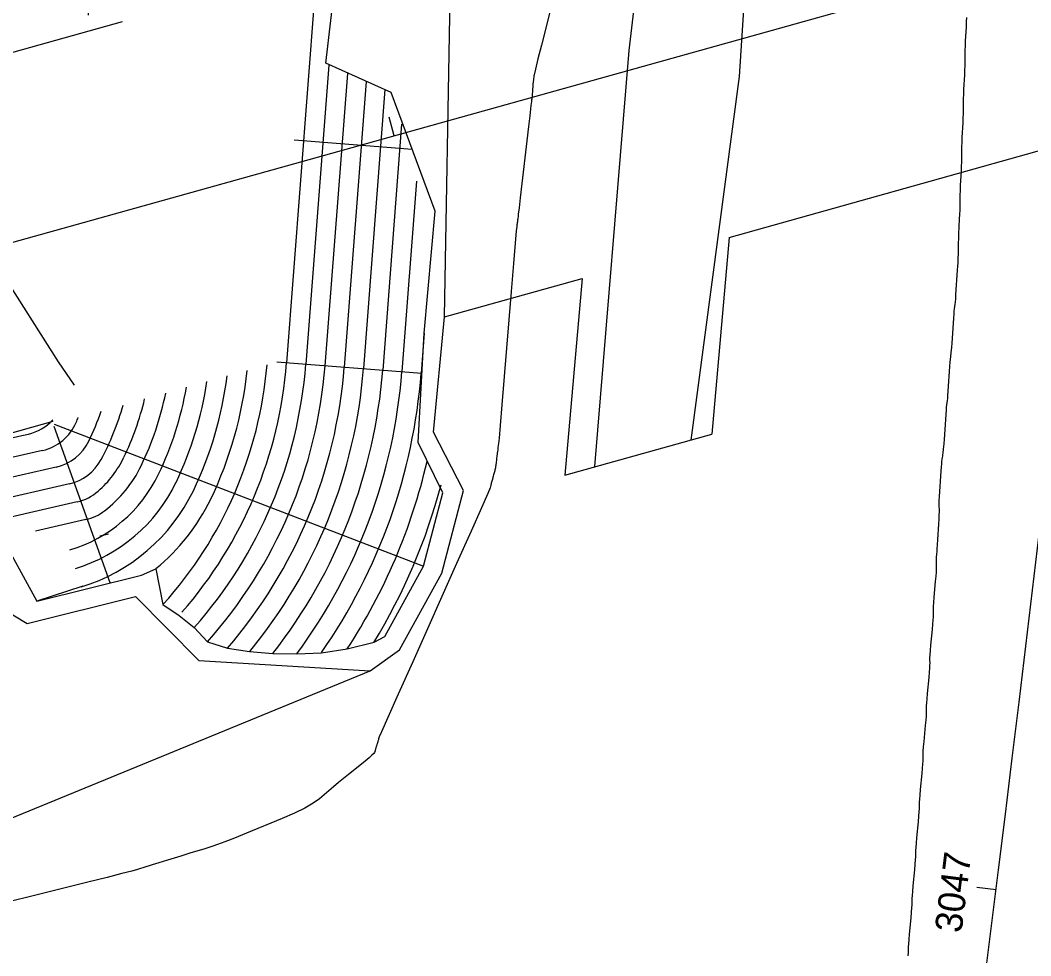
# Model space of a CAD drawing. Extents: x 1512289 to 1544686, y 552531 to 589211.
# Drawn here: x 1543120 to 1543224.9, y 587283 to 587380.1 of the extents above; entities that cross this region are included whole.
import ezdxf

# ---------------------------------------------------------------- set-up
doc = ezdxf.new("R2010")
doc.units = 0
for name, color, linetype in [('DR_X_Flood_Boundary', 7, 'Continuous'), ('DT_P_Break_Line', 7, 'Continuous'), ('DT_P_Contour_Major', 7, 'Continuous'), ('DT_P_Contour_Minor', 7, 'Continuous'), ('DT_P_Graded_Shoulder', 7, 'Continuous'), ('DT_P_Slope_Break_Line', 7, 'Continuous'), ('GE_X_CL_20', 7, 'Continuous'), ('GK_Visualization', 7, 'Continuous'), ('RD_P_Fence', 7, 'Continuous'), ('RW_P_Const_Limits', 7, 'Continuous'), ('SC_Scratch1', 7, 'Continuous'), ('SC_Scratch2', 7, 'Continuous')]:
    doc.layers.add(name, color=color, linetype=linetype)

msp = doc.modelspace()

# ---------------------------------------------------------------- linework, layer by layer
at = {"layer": 'DR_X_Flood_Boundary'}
for points in [[(1543175.17, 587381.74), (1543174.09, 587377.47), (1543173.73, 587376.04), (1543173.47, 587374.97), (1543173.31, 587374.26), (1543173.25, 587373.91), (1543173.21, 587373.44), (1543173.2, 587373.27), (1543173.18, 587373.1), (1543173.17, 587372.93), (1543173.16, 587372.76), (1543173.12, 587372.3), (1543173.11, 587372.15), (1543173.11, 587372.05), (1543173.1, 587371.98), (1543173.1, 587371.96), (1543173.1, 587371.96), (1543173.1, 587371.94), (1543173.09, 587371.88), (1543173.07, 587371.78), (1543173.06, 587371.64), (1543173, 587371.22), (1543172.95, 587370.87), (1543172.87, 587370.14), (1543172.74, 587369.04), (1543172.57, 587367.56), (1543172.06, 587363.12), (1543171.89, 587361.65), (1543171.77, 587360.59), (1543171.69, 587359.93), (1543171.66, 587359.68), (1543171.64, 587359.54), (1543171.64, 587359.49), (1543171.63, 587359.44), (1543171.62, 587359.39), (1543171.62, 587359.34), (1543171.6, 587359.22), (1543171.59, 587359.17), (1543171.59, 587359.12), (1543171.58, 587359.08), (1543171.58, 587359.04), (1543171.56, 587358.92), (1543171.55, 587358.88), (1543171.55, 587358.83), (1543171.54, 587358.79), (1543171.54, 587358.75), (1543171.52, 587358.65), (1543171.48, 587358.2), (1543171.38, 587356.93), (1543171.2, 587354.84), (1543170.96, 587351.93), (1543170.22, 587343.09), (1543169.98, 587340.16), (1543169.8, 587338.03), (1543169.69, 587336.7), (1543169.63, 587336.15), (1543169.58, 587335.75), (1543169.56, 587335.6), (1543169.55, 587335.45), (1543169.53, 587335.31), (1543169.51, 587335.17), (1543169.46, 587334.79), (1543169.44, 587334.65), (1543169.43, 587334.51), (1543169.41, 587334.38), (1543169.39, 587334.24), (1543169.35, 587333.89), (1543169.33, 587333.77), (1543169.32, 587333.69), (1543169.31, 587333.63), (1543169.31, 587333.61), (1543169.3, 587333.59), (1543169.3, 587333.57), (1543169.29, 587333.52), (1543169.27, 587333.44), (1543169.24, 587333.33), (1543169.15, 587333.01), (1543169.12, 587332.89), (1543169.09, 587332.78), (1543169.06, 587332.66), (1543169.03, 587332.55), (1543168.95, 587332.25), (1543168.92, 587332.14), (1543168.89, 587332.03), (1543168.86, 587331.93), (1543168.84, 587331.82), (1543168.76, 587331.54), (1543168.53, 587330.98), (1543167.87, 587329.48), (1543166.79, 587327.05), (1543165.29, 587323.7), (1543160.73, 587313.51), (1543159.23, 587310.16), (1543158.15, 587307.75), (1543157.49, 587306.26), (1543157.26, 587305.72), (1543157.2, 587305.51), (1543157.17, 587305.43), (1543157.15, 587305.35), (1543157.13, 587305.28), (1543157.1, 587305.2), (1543157.05, 587305.01), (1543157.02, 587304.93), (1543157, 587304.86), (1543156.98, 587304.79), (1543156.96, 587304.72), (1543156.91, 587304.54), (1543156.89, 587304.47), (1543156.87, 587304.41), (1543156.85, 587304.34), (1543156.83, 587304.28), (1543156.77, 587304.11), (1543156.7, 587304.01), (1543156.51, 587303.82), (1543156.21, 587303.56), (1543155.8, 587303.22), (1543154.55, 587302.2), (1543154.07, 587301.81), (1543153.57, 587301.4), (1543153.05, 587300.98), (1543152.52, 587300.53), (1543151.06, 587299.31), (1543150.4, 587298.84), (1543149.54, 587298.34), (1543148.47, 587297.81), (1543147.19, 587297.26), (1543143.5, 587295.74), (1543142.25, 587295.23), (1543141.25, 587294.84), (1543140.5, 587294.56), (1543140.01, 587294.39), (1543139.05, 587294.09), (1543138.69, 587293.98), (1543138.33, 587293.87), (1543137.97, 587293.76), (1543137.62, 587293.65), (1543136.69, 587293.36), (1543136.34, 587293.25), (1543135.99, 587293.15), (1543135.65, 587293.04), (1543135.3, 587292.94), (1543134.4, 587292.66), (1543134.06, 587292.55), (1543133.72, 587292.45), (1543133.39, 587292.34), (1543133.06, 587292.24), (1543132.18, 587291.97), (1543131.61, 587291.81), (1543130.57, 587291.54), (1543129.04, 587291.15), (1543127.04, 587290.65), (1543121.08, 587289.17), (1543119.1, 587288.68)], [(1543218.18, 587380.33), (1543218.16, 587379.91), (1543218.14, 587379.39), (1543218.06, 587377.88), (1543218.04, 587377.37), (1543218.02, 587376.94), (1543218.01, 587376.62), (1543218.01, 587376.39), (1543218.02, 587375.9), (1543218.02, 587375.67), (1543218.01, 587375.34), (1543217.99, 587374.92), (1543217.96, 587374.4), (1543217.89, 587372.89), (1543217.86, 587372.37), (1543217.85, 587371.95), (1543217.84, 587371.62), (1543217.83, 587371.39), (1543217.84, 587370.9), (1543217.84, 587370.67), (1543217.83, 587370.34), (1543217.82, 587369.92), (1543217.79, 587369.4), (1543217.71, 587367.89), (1543217.69, 587367.37), (1543217.67, 587366.95), (1543217.66, 587366.63), (1543217.66, 587366.39), (1543217.67, 587365.91), (1543217.67, 587365.68), (1543217.66, 587365.35), (1543217.64, 587364.93), (1543217.62, 587364.41), (1543217.54, 587362.9), (1543217.52, 587362.38), (1543217.5, 587361.96), (1543217.49, 587361.63), (1543217.49, 587361.4), (1543217.49, 587360.91), (1543217.49, 587360.68), (1543217.48, 587360.36), (1543217.47, 587359.93), (1543217.44, 587359.42), (1543217.37, 587357.9), (1543217.34, 587357.39), (1543217.32, 587356.98), (1543217.32, 587356.68), (1543217.31, 587356.49), (1543217.32, 587356.12), (1543217.32, 587355.98), (1543217.31, 587355.83), (1543217.31, 587355.68), (1543217.3, 587355.52), (1543217.28, 587355.08), (1543217.27, 587354.86), (1543217.25, 587354.55), (1543217.22, 587354.13), (1543217.19, 587353.61), (1543217.09, 587352.09), (1543217.06, 587351.57), (1543217.03, 587351.15), (1543217, 587350.83), (1543216.97, 587350.6), (1543216.91, 587350.13), (1543216.88, 587349.9), (1543216.86, 587349.57), (1543216.82, 587349.15), (1543216.79, 587348.62), (1543216.69, 587347.09), (1543216.65, 587346.57), (1543216.62, 587346.15), (1543216.59, 587345.82), (1543216.57, 587345.6), (1543216.51, 587345.14), (1543216.48, 587344.92), (1543216.46, 587344.59), (1543216.42, 587344.17), (1543216.39, 587343.64), (1543216.29, 587342.09), (1543216.25, 587341.57), (1543216.22, 587341.14), (1543216.2, 587340.82), (1543216.17, 587340.6), (1543216.11, 587340.15), (1543216.09, 587339.93), (1543216.06, 587339.61), (1543216.03, 587339.18), (1543215.99, 587338.65), (1543215.89, 587337.09), (1543215.86, 587336.56), (1543215.83, 587336.14), (1543215.8, 587335.82), (1543215.78, 587335.6), (1543215.72, 587335.17), (1543215.7, 587335.01), (1543215.68, 587334.85), (1543215.66, 587334.71), (1543215.64, 587334.57), (1543215.6, 587334.22), (1543215.58, 587334.02), (1543215.55, 587333.72), (1543215.52, 587333.3), (1543215.49, 587332.77), (1543215.39, 587331.19), (1543215.35, 587330.66), (1543215.33, 587330.23), (1543215.32, 587329.91), (1543215.32, 587329.7), (1543215.34, 587329.29), (1543215.34, 587329.08), (1543215.33, 587328.76), (1543215.31, 587328.33), (1543215.27, 587327.79), (1543215.17, 587326.2), (1543215.14, 587325.65), (1543215.11, 587325.23), (1543215.09, 587324.91), (1543215.08, 587324.71), (1543215.05, 587324.33), (1543215.04, 587324.18), (1543215.04, 587324.03), (1543215.04, 587323.89), (1543215.04, 587323.74), (1543215.05, 587323.34), (1543215.05, 587323.13), (1543215.03, 587322.82), (1543215, 587322.38), (1543214.95, 587321.84), (1543214.81, 587320.23), (1543214.76, 587319.68), (1543214.73, 587319.25), (1543214.71, 587318.94), (1543214.71, 587318.74), (1543214.72, 587318.36), (1543214.71, 587318.16), (1543214.69, 587317.84), (1543214.66, 587317.41), (1543214.61, 587316.86), (1543214.46, 587315.23), (1543214.42, 587314.68), (1543214.38, 587314.25), (1543214.36, 587313.94), (1543214.36, 587313.74), (1543214.37, 587313.38), (1543214.36, 587313.18), (1543214.34, 587312.86), (1543214.31, 587312.43), (1543214.26, 587311.87), (1543214.11, 587310.24), (1543214.06, 587309.68), (1543214.03, 587309.25), (1543214.01, 587308.94), (1543214.01, 587308.75), (1543214.01, 587308.4), (1543214.01, 587308.2), (1543213.99, 587307.89), (1543213.95, 587307.45), (1543213.9, 587306.89), (1543213.75, 587305.24), (1543213.7, 587304.68), (1543213.67, 587304.25), (1543213.65, 587303.94), (1543213.64, 587303.75), (1543213.65, 587303.41), (1543213.64, 587303.23), (1543213.62, 587302.91), (1543213.59, 587302.48), (1543213.54, 587301.91), (1543213.39, 587300.25), (1543213.34, 587299.69), (1543213.3, 587299.25), (1543213.28, 587298.94), (1543213.27, 587298.76), (1543213.28, 587298.43), (1543213.27, 587298.25), (1543213.25, 587297.94), (1543213.22, 587297.5), (1543213.17, 587296.93), (1543213.01, 587295.26), (1543212.96, 587294.69), (1543212.93, 587294.26), (1543212.91, 587293.95), (1543212.9, 587293.77), (1543212.9, 587293.45), (1543212.9, 587293.27), (1543212.87, 587292.96), (1543212.84, 587292.52), (1543212.79, 587291.95), (1543212.63, 587290.27), (1543212.58, 587289.7), (1543212.55, 587289.26), (1543212.52, 587288.95), (1543212.52, 587288.77), (1543212.52, 587288.47), (1543212.51, 587288.29), (1543212.49, 587287.98), (1543212.45, 587287.54), (1543212.4, 587286.97), (1543212.25, 587285.27), (1543212.2, 587284.7), (1543212.16, 587284.26), (1543212.14, 587283.96), (1543212.13, 587283.78), (1543212.13, 587283.49), (1543212.13, 587283.32), (1543212.1, 587283.01)]]:
    msp.add_lwpolyline(points, dxfattribs=at)
at = {"layer": 'DT_P_Break_Line'}
for p, q in [((1543161.92, 587347.6), (1543163.06, 587360.24)), ((1543115.69, 587330.7), (1543121.75, 587319.81)), ((1543161.87, 587323.43), (1543163.87, 587331.04)), ((1543157.84, 587316.12), (1543161.87, 587323.43)), ((1543121.75, 587319.81), (1543132.61, 587322.5)), ((1543156.74, 587315.55), (1543157.84, 587316.12))]:
    msp.add_line(p, q, dxfattribs=at)
for points in [[(1543163.06, 587360.24), (1543158.5, 587372.57), (1543151.72, 587375.59), (1543153.27, 587388.9), (1543151.01, 587390.11), (1543150.36, 587390.72), (1543150.36, 587402.78), (1543149.35, 587406.26), (1543145.28, 587406.98), (1543127.72, 587405.59), (1543127.07, 587380.6)], [(1543163.87, 587331.04), (1543161.29, 587336.26), (1543161.92, 587347.6)], [(1543132.61, 587322.5), (1543134.07, 587323.16), (1543134.82, 587319.44), (1543136.49, 587318.3), (1543138.07, 587317.07), (1543139.43, 587315.59)], [(1543139.43, 587315.59), (1543141.51, 587314.94), (1543143.82, 587314.57), (1543146.23, 587314.38), (1543148.72, 587314.35), (1543151.26, 587314.45), (1543153.94, 587314.86), (1543156.74, 587315.55)]]:
    msp.add_lwpolyline(points, dxfattribs=at)
at = {"layer": 'DT_P_Contour_Major'}
for p, q in [((1543153.96, 587374.55), (1543151.63, 587344.22)), ((1543161.92, 587347.6), (1543161.6, 587343.46))]:
    msp.add_line(p, q, dxfattribs=at)
msp.add_lwpolyline([(1543125.12, 587331.96), (1543108.3, 587328.1)], dxfattribs=at)
for centre, radius, start, end in [((1543103.24, 587347.94), 48.54, 318.2105, 355.6111), ((1543103.24, 587347.94), 38.54, 334.354, 352.8806), ((1543103.24, 587347.94), 58.54, 325.153, 355.6111), ((1543103.24, 587347.94), 28.54, 331.8609, 344.1575), ((1543123.99, 587336.84), 5, 282.9567, 331.8609), ((1543120.85, 587339.48), 19, 286.7518, 334.354)]:
    msp.add_arc(centre, radius, start, end, dxfattribs=at)
at = {"layer": 'DT_P_Contour_Minor'}
for p, q in [((1543151.14, 587390.04), (1543147.65, 587344.53)), ((1543152.02, 587375.39), (1543149.64, 587344.38)), ((1543155.9, 587373.72), (1543153.63, 587344.07)), ((1543157.85, 587372.88), (1543155.62, 587343.92)), ((1543159.58, 587369.29), (1543157.62, 587343.76)), ((1543161.13, 587363.36), (1543159.61, 587343.61)), ((1543126.52, 587321.35), (1543121.75, 587319.81))]:
    msp.add_line(p, q, dxfattribs=at)
for points in [[(1543118.24, 587376.47), (1543117.42, 587373.98), (1543117.2, 587373.15), (1543117.03, 587372.22), (1543116.91, 587371.19), (1543116.86, 587370.06), (1543116.72, 587364.51), (1543116.58, 587358.74), (1543116.64, 587357.53), (1543116.87, 587356.36), (1543117.28, 587355.24), (1543117.86, 587354.17), (1543123.96, 587344.64), (1543125.62, 587342.19)], [(1543111.51, 587334.98), (1543120.2, 587336.98), (1543120.87, 587337.14)], [(1543122.34, 587335.43), (1543117.91, 587334.41), (1543094.99, 587329.13)], [(1543123.76, 587333.7), (1543120.11, 587332.86), (1543081.42, 587323.96)], [(1543125.94, 587330.1), (1543114.95, 587327.58)], [(1543126.84, 587328.26), (1543121.61, 587327.06)], [(1543129.16, 587326.75), (1543128.91, 587326.69), (1543128.26, 587326.54)]]:
    msp.add_lwpolyline(points, dxfattribs=at)
for centre, radius, start, end in [((1543103.24, 587347.94), 42.54, 318.0024, 355.1201), ((1543103.24, 587347.94), 44.54, 318.8798, 355.6111), ((1543103.24, 587347.94), 46.54, 318.4698, 355.6111), ((1543103.24, 587347.94), 50.54, 319.2204, 355.6111), ((1543103.24, 587347.94), 40.54, 334.354, 354.0599), ((1543103.24, 587347.94), 52.54, 320.5744, 355.6111), ((1543103.24, 587347.94), 54.54, 322.0292, 355.6111), ((1543103.24, 587347.94), 56.54, 323.5471, 355.6111), ((1543103.24, 587347.94), 34.54, 334.354, 350.0705), ((1543103.24, 587347.94), 36.54, 334.354, 351.5601), ((1543103.24, 587347.94), 32.54, 334.354, 348.3752), ((1543103.24, 587347.94), 30.54, 334.354, 346.4262), ((1543103.24, 587347.94), 24.54, 336.9873, 338.247), ((1543103.24, 587347.94), 26.54, 334.2332, 341.4767), ((1543119.74, 587342.01), 5, 282.9764, 317.0845), ((1543121.22, 587340.3), 5, 282.9764, 336.9873), ((1543122.64, 587338.58), 5, 282.9764, 334.2332), ((1543120.85, 587339.48), 11, 311.3327, 334.354), ((1543120.85, 587339.48), 13, 307.5142, 334.354), ((1543103.24, 587347.94), 60.54, 326.8766, 346.9537), ((1543120.85, 587339.48), 15, 286.7518, 334.354), ((1543120.85, 587339.48), 17, 286.7518, 334.354), ((1543103.24, 587347.94), 62.54, 328.7666, 345.1163), ((1543124.81, 587334.98), 5, 282.9567, 311.3327), ((1543120.85, 587339.48), 21, 309.0718, 334.354), ((1543125.72, 587333.14), 5, 282.9567, 307.5142)]:
    msp.add_arc(centre, radius, start, end, dxfattribs=at)
at = {"layer": 'DT_P_Graded_Shoulder'}
for p, q in [((1542937, 587325.83), (1543130.63, 587379.93)), ((1542947.23, 587289.23), (1543123.44, 587338.47))]:
    msp.add_line(p, q, dxfattribs=at)
at = {"layer": 'DT_P_Slope_Break_Line'}
for p, q in [((1543148.42, 587367.64), (1543160.67, 587366.7)), ((1543146.65, 587344.61), (1543161.69, 587343.45)), ((1543123.51, 587337.96), (1543129.32, 587321.75)), ((1543123.53, 587338.15), (1543161.87, 587323.43))]:
    msp.add_line(p, q, dxfattribs=at)
at = {"layer": 'GE_X_CL_20'}
for p, q in [((1541212.25, 586824.18), (1543339.29, 587418.51)), ((1543158.82, 587368.08), (1543158.28, 587370.01)), ((1543221.25, 587289.85), (1543219.26, 587290.1))]:
    msp.add_line(p, q, dxfattribs=at)
msp.add_arc((1537339.33, 588021.26), 5927.22, 346.145191, 0.622804, dxfattribs=at)
at = {"layer": 'GK_Visualization'}
msp.add_line((1541212.25, 586824.18), (1543339.29, 587418.51), dxfattribs=at)
msp.add_arc((1537339.33, 588021.26), 5927.22, 346.145191, 0.622804, dxfattribs=at)
msp.add_arc((1537339.33, 588021.26), 5927.22, 346.145191, 0.622804, dxfattribs=at)
at = {"layer": 'RD_P_Fence'}
for points in [[(1543189.61, 587336.51), (1543194.65, 587374.22), (1543197.22, 587414.18), (1543197.48, 587418.99)], [(1543179.62, 587333.76), (1543183.18, 587376.91), (1543187.56, 587414.02), (1543187.65, 587416.24)]]:
    msp.add_lwpolyline(points, dxfattribs=at)
at = {"layer": 'RW_P_Const_Limits'}
for p, q in [((1543193.55, 587357.54), (1543235.93, 587369.38)), ((1543193.55, 587357.54), (1543191.78, 587337.12)), ((1543164.02, 587349.29), (1543178.3, 587353.28)), ((1543178.3, 587353.28), (1543176.53, 587332.86)), ((1543176.53, 587332.86), (1543191.78, 587337.12)), ((1543101.79, 587290.22), (1543156.33, 587312.59))]:
    msp.add_line(p, q, dxfattribs=at)
msp.add_lwpolyline([(1543156.33, 587312.59), (1543159.37, 587314.76), (1543163.74, 587322.69), (1543166, 587331.27), (1543162.88, 587337.32), (1543164.02, 587349.29)], dxfattribs=at)
at = {"layer": 'SC_Scratch1'}
msp.add_lwpolyline([(1543104.88, 587327.07), (1543120.75, 587317.5), (1543131.99, 587320.28), (1543138.55, 587313.64), (1543156.33, 587312.59)], dxfattribs=at)
at = {"layer": 'SC_Scratch2'}
for p, q in [((1543164.02, 587349.29), (1543164.74, 587389.98)), ((1543164.02, 587349.29), (1543164.74, 587389.98)), ((1543101.79, 587290.22), (1543156.33, 587312.59)), ((1543101.79, 587290.22), (1543156.33, 587312.59))]:
    msp.add_line(p, q, dxfattribs=at)
msp.add_lwpolyline([(1543156.33, 587312.59), (1543159.37, 587314.76), (1543163.74, 587322.69), (1543166, 587331.27), (1543162.88, 587337.32), (1543164.02, 587349.29)], dxfattribs=at)
msp.add_lwpolyline([(1543156.33, 587312.59), (1543159.37, 587314.76), (1543163.74, 587322.69), (1543166, 587331.27), (1543162.88, 587337.32), (1543164.02, 587349.29)], dxfattribs=at)

# ---------------------------------------------------------------- texts
at = {"layer": 'GE_X_CL_20'}
msp.add_text('3047', height=2.8, rotation=82.9118, dxfattribs=at).set_placement((1543217.66, 587285.32))

doc.saveas('drawing.dxf')
